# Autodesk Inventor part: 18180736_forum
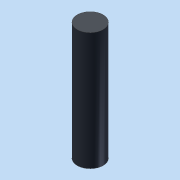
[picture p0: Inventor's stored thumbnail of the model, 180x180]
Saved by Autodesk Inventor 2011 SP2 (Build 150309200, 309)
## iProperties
AfterAnyParamChange0: Volumen
AfterAnyParamChange1: xSchwerpkt
AfterAnyParamChange2: Masse
AfterAnyParamChange3: Oberflaeche
AfterFeatureSuppressionChange0: Volumen
AfterFeatureSuppressionChange1: xSchwerpkt
AfterFeatureSuppressionChange2: Masse
AfterFeatureSuppressionChange3: Oberflaeche
PartBodyChanged0: Volumen
PartBodyChanged1: xSchwerpkt
PartBodyChanged2: Masse
PartBodyChanged3: Oberflaeche
AfterMaterialChange0: Masse
Company: Martin Christ Gefriertrocknungsanlagen GmbH
Created: 2012-11
Part Number: 18180736_forum
User Status: New
Material: ---
Document SubType Name: Modeling
Designer: Hanke , Hankem
Mass: 20.9046 g
Surface Area: 51.5441 cm^2
Volume: 20.9046 cm^3
Density: 1 g/cm^3
Description: Abstandsbolzen für Stellflächenabstand  35 bis 314
2_Benennung: Stellflächen Ø375, beheizt mit LyoBus
Abmessung: siehe Tabelle
Abnahmeprüfzeugnis: ---
Bereich: Bereich_Laboranlagen
PhysMass: 0,021 kg
PhysMaterial: ---
Produktmedienberuehrend: True
Sprache: DE
G_L: 95
G_H: 1
G_W: 18
Abmessung_Text: Ø
Toleranz: mK
Blattanzahl: 1
Abmessung_Norm: lg.
Volumen: 0,000 l
Masse: 0,020 kg
DIM_max: 59
DIM_mid: 18
DIM_min: 18
Ref_Teilenummer_orginal: 18180750
Ref_Benennung_orginal: Abstandsbolzen für Stellflächenabstand 67,5
SF_Abstand: 100
SaveDate: 2012-11-05
SaveTime: 08:15
Oberflaeche: 5154 mm^3
Author: Hankem
Revision Number: .0
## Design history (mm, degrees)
sketch "Skizze1"
  geometry: C1 r 9 at (0, 0); 1 further point
  constraints: 1 centre point, 1 coincident, 1 other
extrude "Extrusion1" new body sketch "Skizze1" taper "d2" = 0 deg
node "Volumenkörper1"
node "Volumenkörpern"
node "Oberflächenkörpern"
other parameters: "G_L" = 95 (computed from l_ges) [user parameter], "G_H" = 1 [user parameter], "G_W" = 18 [user parameter; used in 1 equation term], "d24" = 0.5, "d25" = 2, "d26" = 0, "Volumen" = 0 [user parameter], "Masse" = 0.2 [user parameter], "xSchwerpkt" = 0 [user parameter], "Volumen_Dim" = 1e+07 [user parameter], "ySchwerpkt" = 0 [user parameter], "zSchwerpkt" = 0 [user parameter], "Rx" = 1 deg [user parameter], "Ry" = 0 [user parameter], "Rz" = 0 [user parameter], "DIM_min" = 18 [user parameter], "DIM_mid" = 18 [user parameter], "DIM_max" = 59 [user parameter], "l_ges" = 91.15, "d77" = 0, "Oberflaeche" = 51.54 [user parameter], "Oberflaeche_ipart" = 51.54 [user parameter]
